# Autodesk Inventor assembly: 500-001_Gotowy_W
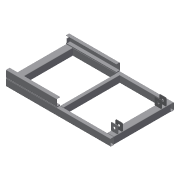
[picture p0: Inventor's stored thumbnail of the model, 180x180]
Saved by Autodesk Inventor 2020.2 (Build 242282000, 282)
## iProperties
Created: 2016-09
Part Number: 500-001_Gotowy_W
Document SubType Name: Assembly
Designer: F.Stasiak
Description: Podstawa
Manager: www.cadconsulting.pl
Company: Fabian Stasiak CAD Consulting
Author: F.Stasiak
Subject: Zbiór ćwiczeń. Autodesk Inventor 2020. Kurs podstawowy
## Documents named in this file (11)
- C:\2020_Kurs_podstawowy\R6 Zespoły\Warsztat\Komponenty\500-001_Gotowy_W.iam
- C:\2020_Kurs_podstawowy\R6 Zespoły\Warsztat\Komponenty\500-01-06.ipt
- C:\2020_Kurs_podstawowy\R6 Zespoły\Warsztat\Komponenty\500-01-07.ipt
- C:\2020_Kurs_podstawowy\R6 Zespoły\Warsztat\Komponenty\EN 10058 - 500-01-08.ipt
- C:\2020_Kurs_podstawowy\R6 Zespoły\Warsztat\Komponenty\DIN 120x60x4 500-01-01.ipt
- DIN 120x60x4 900-01-1.ipt
- C:\2020_Kurs_podstawowy\R6 Zespoły\Warsztat\Komponenty\DIN 120x60x4 500-01-02.ipt
- DIN 120x60x4 900-01-02.ipt
- C:\2020_Kurs_podstawowy\R6 Zespoły\Warsztat\Komponenty\DIN 120x60x4 500-01-04.ipt
- DIN 120x60x4 900-01-04.ipt
- C:\2020_Kurs_podstawowy\R6 Zespoły\Warsztat\Komponenty\500-01-08.ipt
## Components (15 placed, 7 different names)
1. 500-01-06:1
2. 500-01-06:2
3. 500-01-07:4 — Zestawiający:24, Zestawiający:25, Zestawiający:27, Równoległy:18
4. EN 10058 - 500-01-08:1
5. EN 10058 - 500-01-08:2
6. DIN 120x60x4 500-01-01:1 — Zestawiający:18, Równoległy:20
7. DIN 120x60x4 500-01-02:1
8. DIN 120x60x4 500-01-04:1 — Zestawiający:19
9. DIN 120x60x4 500-01-01:2 — Zestawiający:20, Równoległy:19
10. DIN 120x60x4 500-01-04:2 — Zestawiający:21, Zestawiający:25, Równoległy:18, Zestawiający:28, Zestawiający:32, Zestawiający:33
11. 500-01-08:1
12. 500-01-08:2
13. 500-01-07:5 — Zestawiający:24, Zestawiający:27, Zestawiający:28, Zestawiający:31, Równoległy:19
14. 500-01-07:6 — Zestawiający:29, Zestawiający:30, Zestawiający:31, Zestawiający:32, Równoległy:20
15. 500-01-07:7 — Zestawiający:29, Zestawiający:30, Zestawiający:33
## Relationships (16: Mate 13, Flush 3)
- Zestawiający:18 [Mate]: DIN 120x60x4 500-01-01:1
- Zestawiający:19 [Mate]: DIN 120x60x4 500-01-04:1
- Zestawiający:20 [Mate]: DIN 120x60x4 500-01-01:2
- Zestawiający:21 [Mate]: DIN 120x60x4 500-01-04:2
- Zestawiający:24 [Mate]: 500-01-07:4 ↔ 500-01-07:5
- Zestawiający:25 [Mate]: 500-01-07:4 ↔ DIN 120x60x4 500-01-04:2
- Zestawiający:27 [Mate]: 500-01-07:4 ↔ 500-01-07:5
- Równoległy:18 [Flush]: 500-01-07:4 ↔ DIN 120x60x4 500-01-04:2
- Zestawiający:28 [Mate]: DIN 120x60x4 500-01-04:2 ↔ 500-01-07:5
- Zestawiający:29 [Mate]: 500-01-07:6 ↔ 500-01-07:7
- Zestawiający:30 [Mate]: 500-01-07:6 ↔ 500-01-07:7
- Zestawiający:31 [Mate]: 500-01-07:5 ↔ 500-01-07:6
- Zestawiający:32 [Mate]: DIN 120x60x4 500-01-04:2 ↔ 500-01-07:6
- Zestawiający:33 [Mate]: DIN 120x60x4 500-01-04:2 ↔ 500-01-07:7
- Równoległy:19 [Flush]: DIN 120x60x4 500-01-01:2 ↔ 500-01-07:5
- Równoległy:20 [Flush]: DIN 120x60x4 500-01-01:1 ↔ 500-01-07:6
## Named parameters: d0_d28 = 0, d1_d29 = 0, d2_d30 = 0
